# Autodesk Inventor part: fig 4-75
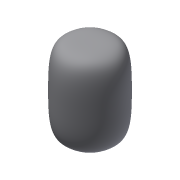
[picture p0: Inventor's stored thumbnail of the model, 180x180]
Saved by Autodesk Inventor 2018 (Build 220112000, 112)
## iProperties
Created: 2012-07
Part Number: fig 4-75
Material: Generic
Document SubType Name: Modeling
Designer: CADCIM
Density: 1 g/cm^3
Appearance: Default
Author: CADCIM
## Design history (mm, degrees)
feature "Form1"
body "Solid1"
body "Solid2"
